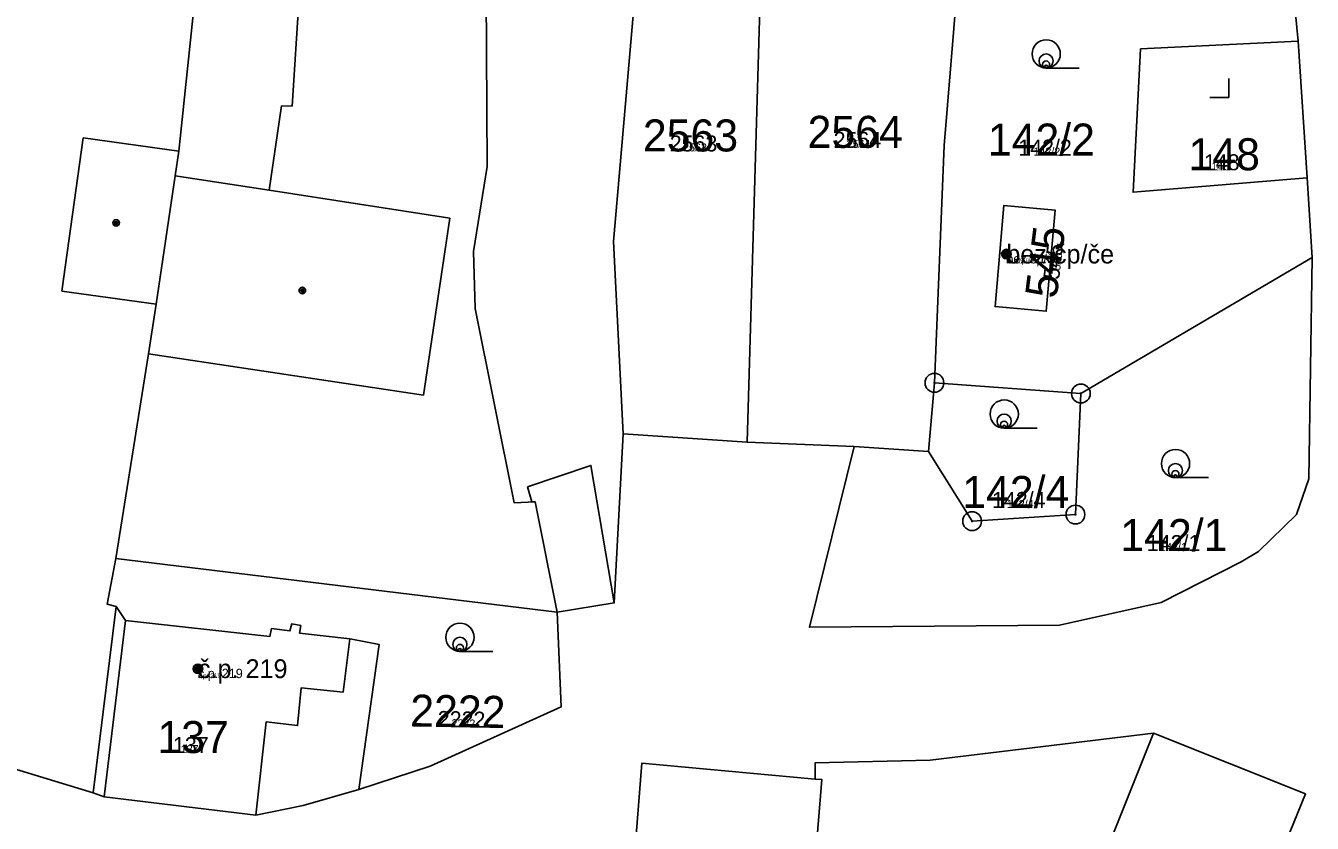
# Model space of a CAD drawing. Extents: x -744652 to -739090, y -980828 to -975855.
# Drawn here: x -742563.4 to -742495.1, y -978711.1 to -978668.8 of the extents above; entities that cross this region are included whole.
import ezdxf

# ---------------------------------------------------------------- set-up
doc = ezdxf.new("R2010")
doc.units = 0
for name, color, linetype in [('KAT_02_hranice parcel', 7, 'Continuous'), ('KAT_03_1000_st čísla parcelní', 7, 'Continuous'), ('KAT_03_1000_čísla parcelní', 7, 'Continuous'), ('KAT_03_1000_čísla popisná', 7, 'Continuous'), ('KAT_03_100_st čísla parcelní', 7, 'Continuous'), ('KAT_03_100_čísla parcelní', 7, 'Continuous'), ('KAT_03_100_čísla popisná', 7, 'Continuous'), ('KAT_03_250_st čísla parcelní', 7, 'Continuous'), ('KAT_03_250_čísla parcelní', 7, 'Continuous'), ('KAT_03_250_čísla popisná', 7, 'Continuous'), ('KAT_03_500_st čísla parcelní', 7, 'Continuous'), ('KAT_03_500_čísla parcelní', 7, 'Continuous'), ('KAT_03_500_čísla popisná', 7, 'Continuous'), ('KAT_04_vnitřní kresba', 7, 'Continuous'), ('KAT_05_1000_značky kultur', 7, 'Continuous'), ('KAT_05_100_značky kultur', 7, 'Continuous'), ('KAT_05_250_značky kultur', 7, 'Continuous'), ('KAT_05_500_značky kultur', 7, 'Continuous'), ('KAT_07_1000_značky budov', 7, 'Continuous'), ('KAT_07_100_značky budov', 7, 'Continuous'), ('KAT_07_500_značky budov', 7, 'Continuous'), ('KAT_10_věcná břemena', 7, 'Continuous'), ('KAT_11_značky bodu BP', 7, 'Continuous'), ('KAT_14_plocha_budovy', 7, 'Continuous')]:
    doc.layers.add(name, color=color, linetype=linetype)

msp = doc.modelspace()

# ---------------------------------------------------------------- linework, layer by layer
at = {"layer": 'KAT_02_hranice parcel'}
for p, q in [((-742497.18, -978656.03), (-742495.86, -978669.57)), ((-742525.13, -978690.87), (-742524.23, -978660.26)), ((-742495.86, -978669.57), (-742495.38, -978676.84)), ((-742495.38, -978676.84), (-742495.11, -978681.06)), ((-742495.11, -978681.06), (-742507.4, -978688.29)), ((-742515.18, -978687.72), (-742515.5, -978691.37)), ((-742515.18, -978687.72), (-742507.4, -978688.29)), ((-742525.13, -978690.87), (-742531.72, -978690.43)), ((-742519.45, -978691.1), (-742525.13, -978690.87)), ((-742515.5, -978691.37), (-742519.45, -978691.1)), ((-742558.66, -978697.05), (-742535.22, -978699.9)), ((-742558.64, -978699.6), (-742559.87, -978709.5)), ((-742559.87, -978709.5), (-742565.2, -978707.88))]:
    msp.add_line(p, q, dxfattribs=at)
for points in [[(-742535.22, -978699.9), (-742536.39, -978694.04), (-742537.51, -978694.09), (-742539.57, -978683.77), (-742539.66, -978680.74), (-742538.93, -978676.23), (-742539, -978667.03), (-742537.87, -978656.25), (-742537.47, -978652.45), (-742540.15, -978652.31), (-742539.85, -978644.03)], [(-742558.66, -978697.05), (-742556.92, -978686.18), (-742556.52, -978683.54), (-742555.52, -978676.73), (-742555.31, -978675.41), (-742554.4, -978666.64), (-742554.07, -978664.41), (-742553.19, -978658.52), (-742553.1, -978658.07), (-742552.6, -978651.73), (-742554.13, -978651.53), (-742553.21, -978644.19)], [(-742531.72, -978690.43), (-742532.23, -978680.22), (-742530.43, -978659.42)], [(-742513.79, -978664.59), (-742514.66, -978675.12), (-742515.18, -978687.72)], [(-742495.86, -978669.57), (-742504.23, -978669.98), (-742504.63, -978677.6), (-742495.38, -978676.84)], [(-742508.76, -978678.55), (-742511.49, -978678.3), (-742511.96, -978683.67), (-742509.24, -978683.92), (-742508.76, -978678.55)], [(-742495.11, -978681.06), (-742495.3, -978692.83), (-742495.95, -978694.71), (-742497.96, -978696.68), (-742498.89, -978697.23), (-742503.13, -978699.4), (-742508.54, -978700.6), (-742521.82, -978700.71), (-742519.45, -978691.1)], [(-742507.4, -978688.29), (-742507.69, -978694.72), (-742513.18, -978695.07), (-742515.5, -978691.37)], [(-742531.72, -978690.43), (-742532.19, -978699.41), (-742535.22, -978699.9)], [(-742558.64, -978699.6), (-742559.13, -978699.48), (-742558.66, -978697.05)], [(-742545.75, -978709.32), (-742544.67, -978701.63), (-742546.13, -978701.34), (-742546.23, -978701.33), (-742548.9, -978701.02), (-742548.84, -978700.62), (-742549.32, -978700.53), (-742549.42, -978700.9), (-742550.4, -978700.78), (-742550.48, -978701.19), (-742558.15, -978700.35), (-742558.64, -978699.6)], [(-742535.22, -978699.9), (-742535, -978704.93), (-742541.96, -978708.09), (-742545.75, -978709.32)], [(-742503.55, -978706.34), (-742515.41, -978707.77), (-742521.52, -978707.91), (-742521.51, -978708.77)], [(-742503.55, -978706.34), (-742508.63, -978719.04), (-742513.76, -978716.77), (-742515.05, -978719.88), (-742516.78, -978719.16), (-742518.38, -978722.9), (-742516.57, -978723.65), (-742511.29, -978725.73), (-742512.43, -978728.57), (-742504.45, -978731.62)], [(-742503.55, -978706.34), (-742495.47, -978709.56), (-742504.45, -978731.62)], [(-742532.24, -978727.28), (-742530.72, -978707.92), (-742521.51, -978708.77)], [(-742522.73, -978728.12), (-742521.17, -978708.79), (-742521.51, -978708.77)], [(-742545.75, -978709.32), (-742548.71, -978710.18), (-742551.23, -978710.69), (-742559.29, -978709.72), (-742559.87, -978709.5)]]:
    msp.add_lwpolyline(points, dxfattribs=at)
at = {"layer": 'KAT_03_1000_čísla popisná'}
for centre in [(-742511.36, -978680.88), (-742511.36, -978680.88), (-742554.3, -978702.91), (-742554.3, -978702.91)]:
    msp.add_circle(centre, 0.25, dxfattribs=at)
at = {"layer": 'KAT_03_100_čísla popisná'}
for centre in [(-742511.36, -978680.88), (-742511.36, -978680.88), (-742554.3, -978702.91), (-742554.3, -978702.91)]:
    msp.add_circle(centre, 0.025, dxfattribs=at)
at = {"layer": 'KAT_03_250_čísla popisná'}
for centre in [(-742511.36, -978680.88), (-742511.36, -978680.88), (-742554.3, -978702.91), (-742554.3, -978702.91)]:
    msp.add_circle(centre, 0.0625, dxfattribs=at)
at = {"layer": 'KAT_03_500_čísla popisná'}
for centre in [(-742511.36, -978680.88), (-742511.36, -978680.88), (-742554.3, -978702.91), (-742554.3, -978702.91)]:
    msp.add_circle(centre, 0.125, dxfattribs=at)
at = {"layer": 'KAT_04_vnitřní kresba'}
for p, q in [((-742549.3, -978673.03), (-742548.64, -978662.96)), ((-742549.87, -978673), (-742550.51, -978677.48)), ((-742549.3, -978673.03), (-742549.87, -978673)), ((-742560.4, -978674.71), (-742561.54, -978682.85)), ((-742555.31, -978675.41), (-742560.4, -978674.71)), ((-742550.51, -978677.48), (-742555.52, -978676.73)), ((-742550.51, -978677.48), (-742540.93, -978678.97)), ((-742540.93, -978678.97), (-742542.32, -978688.38)), ((-742561.54, -978682.85), (-742556.52, -978683.54)), ((-742542.32, -978688.38), (-742556.92, -978686.18)), ((-742558.15, -978700.35), (-742559.29, -978709.72)), ((-742546.59, -978704.15), (-742546.23, -978701.33)), ((-742549.01, -978705.93), (-742548.82, -978703.93)), ((-742548.82, -978703.93), (-742546.59, -978704.15)), ((-742551.23, -978710.69), (-742550.68, -978705.74)), ((-742550.68, -978705.74), (-742549.01, -978705.93))]:
    msp.add_line(p, q, dxfattribs=at)
at = {"layer": 'KAT_05_1000_značky kultur'}
for p, q in [((-742509.243, -978671), (-742507.493, -978671)), ((-742499.55, -978672.56), (-742499.55, -978671.56)), ((-742500.551, -978672.56), (-742499.55, -978672.56)), ((-742511.473, -978690.13), (-742509.723, -978690.13)), ((-742502.373, -978692.76), (-742500.623, -978692.76)), ((-742540.383, -978701.99), (-742538.633, -978701.99))]:
    msp.add_line(p, q, dxfattribs=at)
for centre in [(-742509.243, -978670.25), (-742511.473, -978689.38), (-742502.373, -978692.01), (-742540.383, -978701.24)]:
    msp.add_circle(centre, 0.75, dxfattribs=at)
at = {"layer": 'KAT_05_100_značky kultur'}
for p, q in [((-742509.249, -978671), (-742509.074, -978671)), ((-742499.65, -978672.56), (-742499.55, -978672.56)), ((-742499.55, -978672.56), (-742499.55, -978672.46)), ((-742511.479, -978690.13), (-742511.304, -978690.13)), ((-742502.379, -978692.76), (-742502.204, -978692.76)), ((-742540.389, -978701.99), (-742540.214, -978701.99))]:
    msp.add_line(p, q, dxfattribs=at)
for centre in [(-742509.249, -978670.925), (-742511.479, -978690.055), (-742502.379, -978692.685), (-742540.389, -978701.915)]:
    msp.add_circle(centre, 0.075, dxfattribs=at)
at = {"layer": 'KAT_05_250_značky kultur'}
for p, q in [((-742509.248, -978671), (-742508.811, -978671)), ((-742499.8, -978672.56), (-742499.55, -978672.56)), ((-742499.55, -978672.56), (-742499.55, -978672.31)), ((-742511.478, -978690.13), (-742511.041, -978690.13)), ((-742502.378, -978692.76), (-742501.941, -978692.76)), ((-742540.388, -978701.99), (-742539.951, -978701.99))]:
    msp.add_line(p, q, dxfattribs=at)
for centre in [(-742509.248, -978670.812), (-742511.478, -978689.942), (-742502.378, -978692.572), (-742540.388, -978701.802)]:
    msp.add_circle(centre, 0.187, dxfattribs=at)
at = {"layer": 'KAT_05_500_značky kultur'}
for p, q in [((-742509.247, -978671), (-742508.372, -978671)), ((-742499.55, -978672.56), (-742499.55, -978672.06)), ((-742500.051, -978672.56), (-742499.55, -978672.56)), ((-742511.476, -978690.13), (-742510.601, -978690.13)), ((-742502.377, -978692.76), (-742501.502, -978692.76)), ((-742540.387, -978701.99), (-742539.512, -978701.99))]:
    msp.add_line(p, q, dxfattribs=at)
for centre in [(-742509.246, -978670.625), (-742511.476, -978689.755), (-742502.376, -978692.385), (-742540.386, -978701.615)]:
    msp.add_circle(centre, 0.375, dxfattribs=at)
at = {"layer": 'KAT_07_1000_značky budov'}
for centre in [(-742558.647, -978679.229), (-742511.367, -978680.879), (-742548.757, -978682.819), (-742554.307, -978702.909)]:
    msp.add_circle(centre, 0.175, dxfattribs=at)
at = {"layer": 'KAT_07_100_značky budov'}
for centre in [(-742558.641, -978679.23), (-742511.361, -978680.88), (-742548.751, -978682.82), (-742554.301, -978702.91)]:
    msp.add_circle(centre, 0.0175, dxfattribs=at)
at = {"layer": 'KAT_07_500_značky budov'}
for centre, radius in [((-742558.643, -978679.23), 0.0875), ((-742558.642, -978679.23), 0.0438), ((-742511.363, -978680.88), 0.0875), ((-742511.362, -978680.88), 0.0438), ((-742548.753, -978682.82), 0.0875), ((-742548.752, -978682.82), 0.0438), ((-742554.303, -978702.91), 0.0875), ((-742554.302, -978702.91), 0.0438)]:
    msp.add_circle(centre, radius, dxfattribs=at)
at = {"layer": 'KAT_10_věcná břemena'}
msp.add_lwpolyline([(-742536.79, -978693.24), (-742536.56, -978694.05), (-742536.39, -978694.04), (-742535.22, -978699.9), (-742532.19, -978699.41), (-742533.43, -978692.11)], close=True, dxfattribs=at)
at = {"layer": 'KAT_11_značky bodu BP'}
for centre, radius in [((-742515.18, -978687.72), 0.5), ((-742515.18, -978687.72), 0.0303), ((-742507.4, -978688.29), 0.5), ((-742507.4, -978688.29), 0.0303), ((-742513.18, -978695.07), 0.5), ((-742507.69, -978694.72), 0.5), ((-742513.18, -978695.07), 0.0303), ((-742507.69, -978694.72), 0.0303)]:
    msp.add_circle(centre, radius, dxfattribs=at)
at = {"layer": 'KAT_14_plocha_budovy'}
for points in [[(-742511.49, -978678.3), (-742511.96, -978683.67), (-742509.24, -978683.92), (-742508.76, -978678.55)], [(-742558.15, -978700.35), (-742559.29, -978709.72), (-742551.23, -978710.69), (-742550.68, -978705.74), (-742549.01, -978705.93), (-742548.82, -978703.93), (-742546.59, -978704.15), (-742546.23, -978701.33), (-742548.9, -978701.02), (-742548.84, -978700.62), (-742549.32, -978700.53), (-742549.42, -978700.9), (-742550.4, -978700.78), (-742550.48, -978701.19)], [(-742516.78, -978719.16), (-742518.38, -978722.9), (-742516.57, -978723.65), (-742511.29, -978725.73), (-742512.43, -978728.57), (-742504.45, -978731.62), (-742495.47, -978709.56), (-742503.55, -978706.34), (-742508.63, -978719.04), (-742513.76, -978716.77), (-742515.05, -978719.88)], [(-742532.24, -978727.28), (-742522.73, -978728.12), (-742521.17, -978708.79), (-742521.51, -978708.77), (-742530.72, -978707.92)]]:
    msp.add_lwpolyline(points, close=True, dxfattribs=at)

# ---------------------------------------------------------------- texts
at = {"layer": 'KAT_03_1000_st čísla parcelní'}
for s, p in [('148', (-742501.684, -978676.43)), ('137', (-742556.454, -978707.39))]:
    msp.add_text(s, height=1.7, dxfattribs=at).set_placement(p)
msp.add_text('545', height=1.7, rotation=83, dxfattribs=at).set_placement((-742508.687, -978683.283))
at = {"layer": 'KAT_03_1000_čísla parcelní'}
for s, p in [('2563', (-742530.667, -978675.43)), ('2564', (-742521.917, -978675.24)), ('142/2', (-742512.343, -978675.65)), ('142/4', (-742513.703, -978694.37)), ('142/1', (-742505.303, -978696.66))]:
    msp.add_text(s, height=1.7, dxfattribs=at).set_placement(p)
msp.add_text('2222', height=1.7, rotation=359, dxfattribs=at).set_placement((-742543.041, -978705.976))
at = {"layer": 'KAT_03_1000_čísla popisná'}
for s, height, p in [('148', 0.017, (-742500.074, -978676.43)), ('bez čp/če', 1, (-742511.36, -978681.38)), ('č.p. 219', 1, (-742554.3, -978703.41)), ('137', 0.017, (-742554.818, -978707.39))]:
    msp.add_text(s, height=height, dxfattribs=at).set_placement(p)
msp.add_text('545', height=0.017, rotation=83, dxfattribs=at).set_placement((-742508.44, -978681.271))
at = {"layer": 'KAT_03_100_st čísla parcelní'}
for s, p in [('148', (-742500.22, -978676.43)), ('137', (-742554.966, -978707.39))]:
    msp.add_text(s, height=0.17, dxfattribs=at).set_placement(p)
msp.add_text('545', height=0.17, rotation=83, dxfattribs=at).set_placement((-742508.462, -978681.454))
at = {"layer": 'KAT_03_100_čísla parcelní'}
for s, p in [('2563', (-742528.101, -978675.43)), ('2564', (-742519.429, -978675.24)), ('142/2', (-742509.434, -978675.65)), ('142/4', (-742510.86, -978694.37)), ('142/1', (-742502.773, -978696.66))]:
    msp.add_text(s, height=0.17, dxfattribs=at).set_placement(p)
msp.add_text('2222', height=0.17, rotation=359, dxfattribs=at).set_placement((-742540.397, -978706.022))
at = {"layer": 'KAT_03_100_čísla popisná'}
for s, height, p in [('148', 0.0017, (-742500.059, -978676.43)), ('bez čp/če', 0.1, (-742511.36, -978681.38)), ('č.p. 219', 0.1, (-742554.3, -978703.41)), ('137', 0.0017, (-742554.803, -978707.39))]:
    msp.add_text(s, height=height, dxfattribs=at).set_placement(p)
msp.add_text('545', height=0.0017, rotation=83, dxfattribs=at).set_placement((-742508.438, -978681.252))
at = {"layer": 'KAT_03_250_st čísla parcelní'}
for s, p in [('148', (-742500.464, -978676.43)), ('137', (-742555.214, -978707.39))]:
    msp.add_text(s, height=0.425, dxfattribs=at).set_placement(p)
msp.add_text('545', height=0.425, rotation=83, dxfattribs=at).set_placement((-742508.5, -978681.759))
at = {"layer": 'KAT_03_250_čísla parcelní'}
for s, p in [('2563', (-742528.529, -978675.43)), ('2564', (-742519.844, -978675.24)), ('142/2', (-742509.919, -978675.65)), ('142/4', (-742511.334, -978694.37)), ('142/1', (-742503.195, -978696.66))]:
    msp.add_text(s, height=0.425, dxfattribs=at).set_placement(p)
msp.add_text('2222', height=0.425, rotation=359, dxfattribs=at).set_placement((-742540.838, -978706.014))
at = {"layer": 'KAT_03_250_čísla popisná'}
for s, height, p in [('148', 0.00425, (-742500.062, -978676.43)), ('bez čp/če', 0.25, (-742511.36, -978681.38)), ('č.p. 219', 0.25, (-742554.3, -978703.41)), ('137', 0.00425, (-742554.805, -978707.39))]:
    msp.add_text(s, height=height, dxfattribs=at).set_placement(p)
msp.add_text('545', height=0.00425, rotation=83, dxfattribs=at).set_placement((-742508.438, -978681.255))
at = {"layer": 'KAT_03_500_st čísla parcelní'}
for s, p in [('148', (-742500.871, -978676.43)), ('137', (-742555.628, -978707.39))]:
    msp.add_text(s, height=0.85, dxfattribs=at).set_placement(p)
msp.add_text('545', height=0.85, rotation=83, dxfattribs=at).set_placement((-742508.562, -978682.267))
at = {"layer": 'KAT_03_500_čísla parcelní'}
for s, p in [('2563', (-742529.241, -978675.43)), ('2564', (-742520.535, -978675.24)), ('142/2', (-742510.727, -978675.65)), ('142/4', (-742512.124, -978694.37)), ('142/1', (-742503.898, -978696.66))]:
    msp.add_text(s, height=0.85, dxfattribs=at).set_placement(p)
msp.add_text('2222', height=0.85, rotation=359, dxfattribs=at).set_placement((-742541.572, -978706.002))
at = {"layer": 'KAT_03_500_čísla popisná'}
for s, height, p in [('148', 0.0085, (-742500.066, -978676.43)), ('bez čp/če', 0.5, (-742511.36, -978681.38)), ('č.p. 219', 0.5, (-742554.3, -978703.41)), ('137', 0.0085, (-742554.809, -978707.39))]:
    msp.add_text(s, height=height, dxfattribs=at).set_placement(p)
msp.add_text('545', height=0.0085, rotation=83, dxfattribs=at).set_placement((-742508.439, -978681.261))

doc.saveas('drawing.dxf')
